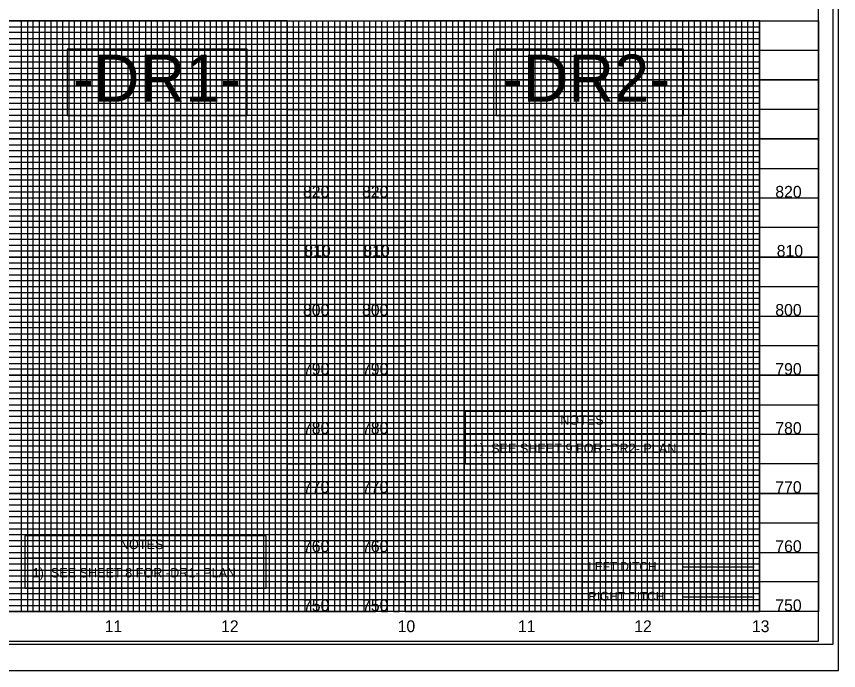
# Model space of a CAD drawing. Extents: x 600491 to 602382, y -54561 to -53461.
# Drawn here: x 601479 to 602175, y -54561 to -54007 of the extents above; entities that cross this region are included whole.
import ezdxf

# ---------------------------------------------------------------- set-up
doc = ezdxf.new("R2010")
doc.units = 0
for name, color, linetype in [('Default', 7, 'Continuous'), ('Exist Vertical Profile Horizontal Axis Label Major', 7, 'Continuous'), ('Exist Vertical Profile Vertical Axis Label', 7, 'Continuous'), ('Prop DSN Text', 7, 'Continuous'), ('Prop Grid Mask', 7, 'Continuous'), ('Prop PFL Ditch Label CELL', 7, 'Continuous'), ('Prop VPI Label', 7, 'Continuous'), ('Sheet Cutting Line CELL', 7, 'Continuous'), ('Sheet DOT Grid CELL', 7, 'Continuous'), ('Sheet Layout Profile Border Port 2', 7, 'Continuous'), ('Sheet Plot Border Inside CELL', 7, 'Continuous'), ('Sheet Plot Border Outside CELL', 7, 'Continuous'), ('Sheet Profile CELL', 7, 'Continuous'), ('Sheet Profile Grid Major CELL', 7, 'Continuous'), ('Sheet Profile Grid Middle CELL', 7, 'Continuous'), ('Sheet Profile Grid Minor CELL', 7, 'Continuous')]:
    doc.layers.add(name, color=color, linetype=linetype)

msp = doc.modelspace()

# ---------------------------------------------------------------- linework, layer by layer
at = {"layer": 'Default'}
for points in [[(601458.32, -54010.99), (601708.27, -54010.99), (601708.27, -54510.99), (601458.32, -54510.99)], [(601808.27, -54010.99), (602158.27, -54010.99), (602158.27, -54510.99), (601808.27, -54510.99)]]:
    msp.add_lwpolyline(points, close=True, dxfattribs=at)
at = {"layer": 'Prop Grid Mask'}
for p, q in [((601708.27, -54035.99), (601758.27, -54035.99)), ((601758.27, -54035.99), (601808.27, -54035.99)), ((601708.27, -54060.99), (601758.27, -54060.99)), ((601758.27, -54060.99), (601808.27, -54060.99)), ((601708.27, -54085.99), (601758.27, -54085.99)), ((601758.27, -54085.99), (601808.27, -54085.99)), ((601708.27, -54110.99), (601758.27, -54110.99)), ((601758.27, -54110.99), (601808.27, -54110.99)), ((601708.27, -54135.99), (601758.27, -54135.99)), ((601758.27, -54135.99), (601808.27, -54135.99)), ((601708.27, -54160.99), (601758.27, -54160.99)), ((601758.27, -54160.99), (601808.27, -54160.99)), ((601708.27, -54185.99), (601758.27, -54185.99)), ((601758.27, -54185.99), (601808.27, -54185.99)), ((601708.27, -54210.99), (601758.27, -54210.99)), ((601758.27, -54210.99), (601808.27, -54210.99)), ((601708.27, -54235.99), (601758.27, -54235.99)), ((601758.27, -54235.99), (601808.27, -54235.99)), ((601708.27, -54260.99), (601758.27, -54260.99)), ((601758.27, -54260.99), (601808.27, -54260.99)), ((601708.27, -54285.99), (601758.27, -54285.99)), ((601758.27, -54285.99), (601808.27, -54285.99)), ((601708.27, -54310.99), (601758.27, -54310.99)), ((601758.27, -54310.99), (601808.27, -54310.99)), ((601708.27, -54335.99), (601758.27, -54335.99)), ((601758.27, -54335.99), (601808.27, -54335.99)), ((601708.27, -54360.99), (601758.27, -54360.99)), ((601758.27, -54360.99), (601808.27, -54360.99)), ((601708.27, -54385.99), (601758.27, -54385.99)), ((601758.27, -54385.99), (601808.27, -54385.99)), ((601708.27, -54410.99), (601758.27, -54410.99)), ((601758.27, -54410.99), (601808.27, -54410.99)), ((601708.27, -54435.99), (601758.27, -54435.99)), ((601758.27, -54435.99), (601808.27, -54435.99)), ((601708.27, -54460.99), (601758.27, -54460.99)), ((601758.27, -54460.99), (601808.27, -54460.99)), ((601708.27, -54485.99), (601758.27, -54485.99)), ((601758.27, -54485.99), (601808.27, -54485.99))]:
    msp.add_line(p, q, dxfattribs=at)
for points in [[(601708.27, -54010.99), (601758.27, -54010.99), (601758.27, -54510.99), (601708.27, -54510.99)], [(601758.27, -54010.99), (601808.27, -54010.99), (601808.27, -54510.99), (601758.27, -54510.99)], [(601521.92, -54091.06), (601674.46, -54091.06), (601674.46, -54035.01), (601521.92, -54035.01)], [(601885.17, -54091.06), (602044.02, -54091.06), (602044.02, -54035.01), (601885.17, -54035.01)], [(601859.08, -54386.01), (602063.43, -54386.01), (602063.43, -54341.72), (601859.08, -54341.72)], [(601859.08, -54360.44), (602063.43, -54360.44), (602063.43, -54341.72), (601859.08, -54341.72)], [(601486.21, -54491.28), (601690.56, -54491.28), (601690.56, -54446.99), (601486.21, -54446.99)], [(601486.21, -54465.71), (601690.56, -54465.71), (601690.56, -54446.99), (601486.21, -54446.99)], [(601958.27, -54460.99), (602108.27, -54460.99), (602108.27, -54485.99), (601958.27, -54485.99)], [(601958.27, -54485.99), (602108.27, -54485.99), (602108.27, -54510.99), (601958.27, -54510.99)]]:
    msp.add_lwpolyline(points, close=True, dxfattribs=at)
at = {"layer": 'Prop PFL Ditch Label CELL'}
for p, q in [((602043.82, -54473.29), (602103.82, -54473.29)), ((601958.27, -54500.99), (601958.27, -54500.99)), ((602043.82, -54498.64), (602103.82, -54498.64))]:
    msp.add_line(p, q, dxfattribs=at)
at = {"layer": 'Sheet Cutting Line CELL'}
msp.add_line((600491.27, -54560.99), (602175.27, -54560.99), dxfattribs=at)
at = {"layer": 'Sheet DOT Grid CELL'}
for p, q in [((600658.27, -54010.99), (602158.16, -54010.99)), ((601508.27, -54010.99), (601508.27, -54510.99)), ((601558.27, -54010.99), (601558.27, -54510.99)), ((601608.27, -54010.99), (601608.27, -54510.99)), ((601658.27, -54010.99), (601658.27, -54510.99)), ((601708.27, -54010.99), (601708.27, -54510.99)), ((601758.27, -54010.99), (601758.27, -54510.99)), ((601808.27, -54010.99), (601808.27, -54510.99)), ((601858.27, -54010.99), (601858.27, -54510.99)), ((601908.27, -54010.99), (601908.27, -54510.99)), ((601958.27, -54010.99), (601958.27, -54510.99)), ((602008.27, -54010.99), (602008.27, -54510.99)), ((602058.27, -54010.99), (602058.27, -54510.99)), ((602108.27, -54010.99), (602108.27, -54510.99)), ((600658.27, -54060.99), (602158.16, -54060.99)), ((600658.27, -54110.99), (602158.16, -54110.99)), ((600658.27, -54160.99), (602158.16, -54160.99)), ((600658.27, -54210.99), (602158.16, -54210.99)), ((600658.27, -54260.99), (602158.16, -54260.99)), ((600658.27, -54310.99), (602158.16, -54310.99)), ((600658.27, -54360.99), (602158.16, -54360.99)), ((600658.27, -54410.99), (602158.16, -54410.99)), ((600658.27, -54460.99), (602158.16, -54460.99))]:
    msp.add_line(p, q, dxfattribs=at)
at = {"layer": 'Sheet Layout Profile Border Port 2'}
for points in [[(601458.27, -54510.99), (601708.27, -54510.99), (601708.27, -54010.99), (601458.27, -54010.99)], [(601808.27, -54510.99), (602108.27, -54510.99), (602108.27, -54010.99), (601808.27, -54010.99)]]:
    msp.add_lwpolyline(points, close=True, dxfattribs=at)
at = {"layer": 'Sheet Plot Border Inside CELL'}
msp.add_lwpolyline([(600504.27, -54538.54), (602170.77, -54538.54), (602170.77, -53483.44), (600504.27, -53483.44)], close=True, dxfattribs=at)
at = {"layer": 'Sheet Plot Border Outside CELL'}
msp.add_lwpolyline([(600491.27, -54560.99), (602175.27, -54560.99), (602175.27, -53460.99), (600491.27, -53460.99)], close=True, dxfattribs=at)
at = {"layer": 'Sheet Profile CELL'}
for p, q in [((600658.27, -54010.99), (602158.27, -54010.99)), ((602158.27, -54510.99), (600658.27, -54510.99)), ((600658.27, -54535.99), (602158.27, -54535.99))]:
    msp.add_line(p, q, dxfattribs=at)
msp.add_lwpolyline([(602158.27, -53485.99), (600658.27, -53485.99), (600658.27, -54535.99), (602158.27, -54535.99)], close=True, dxfattribs=at)
at = {"layer": 'Sheet Profile Grid Major CELL'}
for p, q in [((601458.27, -54010.99), (601508.27, -54010.99)), ((601558.27, -54010.99), (601608.27, -54010.99)), ((601658.27, -54010.99), (601708.27, -54010.99)), ((601758.27, -54010.99), (601808.27, -54010.99)), ((601858.27, -54010.99), (601908.27, -54010.99)), ((601958.27, -54010.99), (602008.27, -54010.99)), ((602058.27, -54010.99), (602108.27, -54010.99)), ((602058.27, -54510.99), (602058.27, -54510.99))]:
    msp.add_line(p, q, dxfattribs=at)
for points in [[(601458.27, -54010.99), (601508.27, -54010.99), (601508.27, -54510.99), (601558.27, -54510.99), (601558.27, -54010.99), (601608.27, -54010.99), (601608.27, -54510.99), (601658.27, -54510.99), (601658.27, -54010.99), (601708.27, -54010.99), (601708.27, -54510.99), (601758.27, -54510.99), (601758.27, -54010.99), (601808.27, -54010.99), (601808.27, -54510.99), (601858.27, -54510.99), (601858.27, -54010.99), (601908.27, -54010.99), (601908.27, -54510.99), (601958.27, -54510.99), (601958.27, -54010.99), (602008.27, -54010.99), (602008.27, -54510.99), (602058.27, -54510.99), (602058.27, -54510.99), (602058.27, -54010.99), (602108.27, -54010.99), (602108.27, -54510.99)], [(602158.27, -54060.99), (600658.27, -54060.99)], [(602158.27, -54110.99), (600658.27, -54110.99), (600658.27, -54160.99), (602158.27, -54160.99)], [(602158.27, -54210.99), (600658.27, -54210.99), (600658.27, -54260.99), (602158.27, -54260.99)], [(602158.27, -54310.99), (600658.27, -54310.99), (600658.27, -54360.99), (602158.27, -54360.99)], [(602158.27, -54410.99), (600658.27, -54410.99), (600658.27, -54410.99), (600658.27, -54460.99), (602158.27, -54460.99)], [(602158.27, -54510.99), (600658.27, -54510.99)]]:
    msp.add_lwpolyline(points, dxfattribs=at)
at = {"layer": 'Sheet Profile Grid Middle CELL'}
for points in [[(601433.27, -54510.99), (601483.27, -54510.99), (601483.27, -54010.99), (601533.27, -54010.99), (601533.27, -54510.99), (601583.27, -54510.99), (601583.27, -54010.99), (601633.27, -54010.99), (601633.27, -54510.99), (601683.27, -54510.99), (601683.27, -54010.99), (601733.27, -54010.99), (601733.27, -54510.99), (601783.27, -54510.99), (601783.27, -54010.99), (601833.27, -54010.99), (601833.27, -54510.99), (601883.27, -54510.99), (601883.27, -54010.99), (601933.27, -54010.99), (601933.27, -54510.99), (601983.27, -54510.99), (601983.27, -54010.99), (602033.27, -54010.99), (602033.27, -54510.99), (602083.27, -54510.99), (602083.27, -54010.99)], [(600658.27, -54035.99), (602158.27, -54035.99)], [(602158.27, -54085.99), (600658.27, -54085.99), (600658.27, -54135.99), (602158.27, -54135.99)], [(602158.27, -54185.99), (600658.27, -54185.99), (600658.27, -54235.99), (602158.27, -54235.99)], [(602158.27, -54285.99), (600658.27, -54285.99), (600658.27, -54335.99), (602158.27, -54335.99)], [(602158.27, -54385.99), (600658.27, -54385.99), (600658.27, -54435.99), (602158.27, -54435.99)], [(602158.27, -54485.99), (600658.27, -54485.99)]]:
    msp.add_lwpolyline(points, dxfattribs=at)
at = {"layer": 'Sheet Profile Grid Minor CELL'}
for p, q in [((600708.27, -54015.99), (602108.27, -54015.99)), ((602108.27, -54020.99), (600708.27, -54020.99)), ((600708.27, -54025.99), (602108.27, -54025.99)), ((602108.27, -54030.99), (600708.27, -54030.99)), ((600708.27, -54040.99), (602108.27, -54040.99)), ((602108.27, -54045.99), (600708.27, -54045.99)), ((600708.27, -54050.99), (602108.27, -54050.99)), ((602108.27, -54055.99), (600708.27, -54055.99)), ((600708.27, -54065.99), (602108.27, -54065.99)), ((602108.27, -54070.99), (600708.27, -54070.99)), ((600708.27, -54075.99), (602108.27, -54075.99)), ((602108.27, -54080.99), (600708.27, -54080.99)), ((600708.27, -54090.99), (602108.27, -54090.99)), ((602108.27, -54095.99), (600708.27, -54095.99)), ((600708.27, -54100.99), (602108.27, -54100.99)), ((602108.27, -54105.99), (600708.27, -54105.99)), ((600708.27, -54115.99), (602108.27, -54115.99)), ((602108.27, -54120.99), (600708.27, -54120.99)), ((600708.27, -54125.99), (602108.27, -54125.99)), ((602108.27, -54130.99), (600708.27, -54130.99)), ((600708.27, -54140.99), (602108.27, -54140.99)), ((602108.27, -54145.99), (600708.27, -54145.99)), ((600708.27, -54150.99), (602108.27, -54150.99)), ((602108.27, -54155.99), (600708.27, -54155.99)), ((600708.27, -54165.99), (602108.27, -54165.99)), ((602108.27, -54170.99), (600708.27, -54170.99)), ((600708.27, -54175.99), (602108.27, -54175.99)), ((602108.27, -54180.99), (600708.27, -54180.99)), ((600708.27, -54190.99), (602108.27, -54190.99)), ((602108.27, -54195.99), (600708.27, -54195.99)), ((600708.27, -54200.99), (602108.27, -54200.99)), ((602108.27, -54205.99), (600708.27, -54205.84)), ((600708.27, -54215.99), (602108.27, -54215.99)), ((602108.27, -54220.99), (600708.27, -54220.99)), ((600708.27, -54225.99), (602108.27, -54225.99)), ((602108.27, -54230.99), (600708.27, -54230.99)), ((600708.27, -54240.99), (602108.27, -54240.99)), ((602108.27, -54245.99), (600708.27, -54245.99)), ((600708.27, -54250.99), (602108.27, -54250.99)), ((602108.27, -54255.99), (600708.27, -54255.99)), ((600708.27, -54265.99), (602108.27, -54265.99)), ((602108.27, -54270.99), (600708.27, -54270.99)), ((600708.27, -54275.99), (602108.27, -54275.99)), ((602108.27, -54280.99), (600708.27, -54280.99)), ((600708.27, -54290.99), (602108.27, -54290.99)), ((602108.27, -54295.99), (600708.27, -54295.99)), ((600708.27, -54300.99), (602108.27, -54300.99)), ((602108.27, -54305.99), (600708.27, -54305.99)), ((600708.27, -54315.99), (602108.27, -54315.99)), ((602108.27, -54320.99), (600708.27, -54320.99)), ((600708.27, -54325.99), (602108.27, -54325.99)), ((602108.27, -54330.99), (600708.27, -54330.99)), ((600708.27, -54340.99), (602108.27, -54340.99)), ((602108.27, -54345.99), (600708.27, -54345.99)), ((600708.27, -54350.99), (602108.27, -54350.99)), ((602108.27, -54355.99), (600708.27, -54355.99)), ((600708.27, -54365.99), (602108.27, -54365.99)), ((602108.27, -54370.99), (600708.27, -54370.99)), ((600708.27, -54375.99), (602108.27, -54375.99)), ((602108.27, -54380.99), (600708.27, -54380.99)), ((600708.27, -54390.99), (602108.27, -54390.99)), ((602108.27, -54395.99), (600708.27, -54395.99)), ((600708.27, -54400.99), (602108.27, -54400.99)), ((602108.27, -54405.99), (600708.27, -54405.99)), ((600708.27, -54415.99), (602108.27, -54415.99)), ((602108.27, -54420.99), (600708.27, -54420.99)), ((600708.27, -54425.99), (602108.27, -54425.99)), ((602108.27, -54430.99), (600708.27, -54430.99)), ((600708.27, -54440.99), (602108.27, -54440.99)), ((602108.27, -54445.99), (600708.27, -54445.99)), ((600708.27, -54450.99), (602108.27, -54450.99)), ((602108.27, -54455.99), (600708.27, -54455.99)), ((600708.27, -54465.99), (602108.27, -54465.99)), ((602108.27, -54470.99), (600708.27, -54470.99)), ((600708.27, -54475.99), (602108.27, -54475.99)), ((602108.27, -54480.99), (600708.27, -54480.99)), ((600708.27, -54490.99), (602108.27, -54490.99)), ((602108.27, -54495.99), (600708.27, -54495.99)), ((600708.27, -54500.99), (602108.27, -54500.99)), ((600708.27, -54505.99), (602108.27, -54505.99)), ((602108.27, -54505.99), (602108.27, -54505.99))]:
    msp.add_line(p, q, dxfattribs=at)
for points in [[(601478.27, -54010.99), (601488.27, -54010.99), (601488.27, -54510.99), (601493.27, -54510.99), (601493.27, -54010.99), (601498.27, -54010.99), (601498.27, -54510.99), (601503.27, -54510.99), (601503.27, -54010.99), (601513.27, -54010.99), (601513.27, -54510.99), (601517.97, -54510.44), (601518.27, -54510.99), (601518.27, -54010.99), (601523.27, -54010.99), (601523.27, -54510.99), (601528.27, -54510.99), (601528.27, -54010.99), (601538.27, -54010.99), (601538.27, -54510.99), (601543.27, -54510.99)], [(601543.27, -54510.99), (601543.27, -54010.99), (601548.27, -54010.99), (601548.27, -54510.99), (601553.27, -54510.99), (601553.27, -54010.99), (601563.27, -54010.99), (601563.27, -54510.99), (601568.27, -54510.99), (601568.27, -54010.99), (601573.27, -54010.99), (601573.27, -54510.99), (601578.27, -54510.99), (601578.27, -54010.99), (601588.27, -54010.99), (601588.27, -54510.99), (601593.27, -54510.99), (601593.27, -54010.99), (601598.27, -54010.99), (601598.27, -54510.99), (601603.27, -54510.99), (601603.27, -54010.99), (601613.27, -54010.99), (601613.27, -54510.99), (601618.27, -54510.99), (601618.27, -54010.99), (601623.27, -54010.99), (601623.27, -54510.99), (601628.27, -54510.99), (601628.27, -54010.99), (601638.27, -54010.99), (601638.27, -54510.99), (601643.27, -54510.99), (601643.27, -54010.99), (601648.27, -54010.99), (601648.27, -54510.99), (601653.27, -54510.99), (601653.27, -54010.99), (601663.27, -54010.99), (601663.27, -54510.99), (601668.27, -54510.99), (601668.27, -54010.99), (601673.27, -54010.99), (601673.27, -54510.99), (601678.27, -54510.99), (601678.27, -54010.99), (601688.27, -54010.99), (601688.27, -54510.99), (601693.27, -54510.99), (601693.27, -54010.99), (601698.27, -54010.99), (601698.27, -54510.99), (601703.27, -54510.99), (601703.27, -54010.99), (601713.27, -54010.99), (601713.27, -54510.99), (601718.27, -54510.99), (601718.27, -54010.99), (601723.27, -54010.99), (601723.27, -54510.99), (601728.27, -54510.99), (601728.27, -54010.99), (601738.27, -54010.99), (601738.27, -54510.99), (601743.27, -54510.99), (601743.27, -54010.99), (601748.27, -54010.99), (601748.27, -54510.99), (601753.27, -54510.99), (601753.27, -54010.99), (601763.27, -54010.99), (601763.27, -54510.99), (601768.27, -54510.99), (601768.27, -54010.99), (601773.27, -54010.99), (601773.27, -54510.99), (601778.27, -54510.99), (601778.27, -54010.99), (601788.27, -54010.99), (601788.27, -54510.99), (601793.27, -54510.99), (601793.27, -54010.99), (601798.27, -54010.99), (601798.27, -54510.99), (601803.27, -54510.99), (601803.27, -54010.99), (601813.27, -54010.99), (601813.27, -54510.99), (601818.27, -54510.99), (601818.27, -54010.99), (601823.27, -54010.99), (601823.27, -54510.99), (601828.27, -54510.99), (601828.27, -54010.99), (601838.27, -54010.99), (601838.27, -54510.99), (601843.27, -54510.99), (601843.27, -54010.99), (601848.27, -54010.99), (601848.27, -54510.99)], [(601848.27, -54510.99), (601853.27, -54510.99), (601853.27, -54010.99), (601863.27, -54010.99), (601863.27, -54510.99), (601868.27, -54510.99), (601868.27, -54010.99), (601873.27, -54010.99), (601873.27, -54510.99), (601878.27, -54510.99), (601878.27, -54010.99), (601888.27, -54010.99), (601888.27, -54510.99), (601893.27, -54510.99), (601893.27, -54010.99), (601898.27, -54010.99), (601898.27, -54510.99), (601903.27, -54510.99), (601903.27, -54010.99), (601913.27, -54010.99), (601913.27, -54510.99), (601918.27, -54510.99), (601918.27, -54010.99), (601923.27, -54010.99), (601923.27, -54510.99), (601928.27, -54510.99), (601928.27, -54010.99), (601938.27, -54010.99), (601938.27, -54510.99), (601943.27, -54510.99), (601943.27, -54010.99), (601948.27, -54010.99), (601948.27, -54510.99), (601953.27, -54510.99), (601953.27, -54010.99), (601963.27, -54010.99), (601963.27, -54510.99), (601968.27, -54510.99), (601968.27, -54010.99), (601973.27, -54010.99), (601973.27, -54510.99), (601978.27, -54510.99), (601978.27, -54010.99), (601988.27, -54010.99), (601988.27, -54510.99), (601993.27, -54510.99), (601993.27, -54010.99), (601998.27, -54010.99), (601998.27, -54510.99), (602003.27, -54510.99), (602003.27, -54010.99), (602013.27, -54010.99), (602013.27, -54510.99), (602018.27, -54510.99), (602018.27, -54010.99), (602023.27, -54010.99), (602023.27, -54510.99), (602028.27, -54510.99), (602028.27, -54010.99), (602038.27, -54010.99), (602038.27, -54510.99), (602043.27, -54510.99), (602043.27, -54010.99), (602048.27, -54010.99), (602048.27, -54510.99), (602053.27, -54510.99), (602053.27, -54010.99), (602063.27, -54010.99), (602063.27, -54510.99), (602068.27, -54510.99), (602068.27, -54010.99), (602073.27, -54010.99), (602073.27, -54510.99), (602078.27, -54510.99), (602078.27, -54010.99), (602088.27, -54010.99), (602088.27, -54510.99), (602093.27, -54510.99), (602093.27, -54010.99), (602098.27, -54010.99), (602098.27, -54510.99), (602103.27, -54510.99), (602103.27, -54010.99), (602108.27, -54010.99)]]:
    msp.add_lwpolyline(points, dxfattribs=at)

# ---------------------------------------------------------------- texts
at = {"layer": 'Exist Vertical Profile Horizontal Axis Label Major'}
for s, p in [('11', (601553.75, -54528.49)), ('12', (601652.31, -54528.49)), ('10', (601801.86, -54528.49)), ('11', (601903.7, -54528.49)), ('12', (602002.24, -54528.49)), ('13', (602101.92, -54528.49))]:
    msp.add_text(s, height=10, dxfattribs=at).set_placement(p)
at = {"layer": 'Exist Vertical Profile Vertical Axis Label'}
for s, p in [('820', (601721.7, -54160.74)), ('820', (601771.7, -54160.74)), ('820', (602121.7, -54160.74)), ('810', (601722.9, -54210.74)), ('810', (601772.9, -54210.74)), ('810', (602122.9, -54210.74)), ('800', (601721.7, -54260.74)), ('800', (601771.7, -54260.74)), ('800', (602121.7, -54260.74)), ('790', (601721.7, -54310.74)), ('790', (601771.7, -54310.74)), ('790', (602121.7, -54310.74)), ('780', (601721.7, -54360.74)), ('780', (601771.7, -54360.74)), ('780', (602121.7, -54360.74)), ('770', (601721.7, -54410.74)), ('770', (601771.7, -54410.74)), ('770', (602121.7, -54410.74)), ('760', (601721.7, -54460.74)), ('760', (601771.7, -54460.74)), ('760', (602121.7, -54460.74)), ('750', (601721.7, -54510.74)), ('750', (601771.7, -54510.74)), ('750', (602121.7, -54510.74))]:
    msp.add_text(s, height=10, dxfattribs=at).set_placement(p)
at = {"layer": 'Prop DSN Text'}
for s, p in [('NOTES', (601939.51, -54352.91)), ('1)  SEE SHEET 9 FOR -DR2- PLAN', (601865.56, -54376.92)), ('NOTES', (601566.63, -54458.18)), ('1)  SEE SHEET 8 FOR -DR1- PLAN', (601492.68, -54482.18))]:
    msp.add_text(s, height=8, dxfattribs=at).set_placement(p)
at = {"layer": 'Prop PFL Ditch Label CELL'}
for s, p in [('LEFT DITCH', (601963.27, -54476.69)), ('RIGHT DITCH', (601963.27, -54501.89))]:
    msp.add_text(s, height=7.485, dxfattribs=at).set_placement(p)
at = {"layer": 'Prop VPI Label'}
for s, p in [('-DR1-', (601526.82, -54079.56)), ('-DR2-', (601890.06, -54079.56))]:
    msp.add_text(s, height=40, dxfattribs=at).set_placement(p)

doc.saveas('drawing.dxf')
